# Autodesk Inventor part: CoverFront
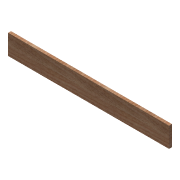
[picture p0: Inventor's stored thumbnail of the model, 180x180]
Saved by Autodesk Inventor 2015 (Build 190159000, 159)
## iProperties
Created: 2016-02
Part Number: CoverFront
Material: Wood (Birch)
Document SubType Name: Modeling
Designer: Hafliði
Density: 0.55 g/cm^3
Appearance: Birch - Natural Polished
Mass: 215.6 g
Surface Area: 910 cm^2
Volume: 392 cm^3
Author: Hafliði
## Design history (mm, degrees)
sketch "Sketch1"
  geometry: L1 (-280, 35)-(280, 35); L2 (280, 35)-(280, -35); L3 (280, -35)-(-280, -35); L4 (-280, -35)-(-280, 35); L5 (-280, 35)-(280, -35); L6 (280, 35)-(-280, -35); 1 further point
  constraints: 12 end point, 2 midpoint, 2 parallel, 1 horizontal, 1 perpendicular
  dimensions: "d0" = 560 distance of L2.end L3.end; "d1" = 70 distance of L1.end L2.end
extrude "Extrusion1" new body sketch "Sketch1" distance "d2" = 10; taper "d3" = 0 deg
body "Solid1"
